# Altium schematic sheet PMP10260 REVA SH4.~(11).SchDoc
size 431 x 279 mm; Date: Not shown in title block; ApprovedBy: Not shown in title block; CheckedBy: Not shown in title block; Author: Not shown in title block; CompanyName: Not shown in title block; Engineer: Not shown in title block; Organization: Not shown in title block; Address1: Not shown in title block; Address2: Not shown in title block; Address3: Not shown in title block; Address4: Not shown in title block; DocumentNumber: 4; Revision: Use project parameter SCH_Rev; SheetNumber: 4; SheetTotal: 4; PageSetup: Record=PageOptions|CenterHorizontal=True|CenterVertical=True|PrintScale=1.00|XCorrection=1.00|YCorrection=1.00|PrintKind=0|BorderSize=5000000|LeftOffset=0|BottomOffset=0|Orientation=2|PaperLength=1000|PaperWidth=1000|Scale=100|PaperSource=15|PrintQuality=600|MediaType=1|DitherType=10|PaperKind=Letter|PrintScaleMode=1
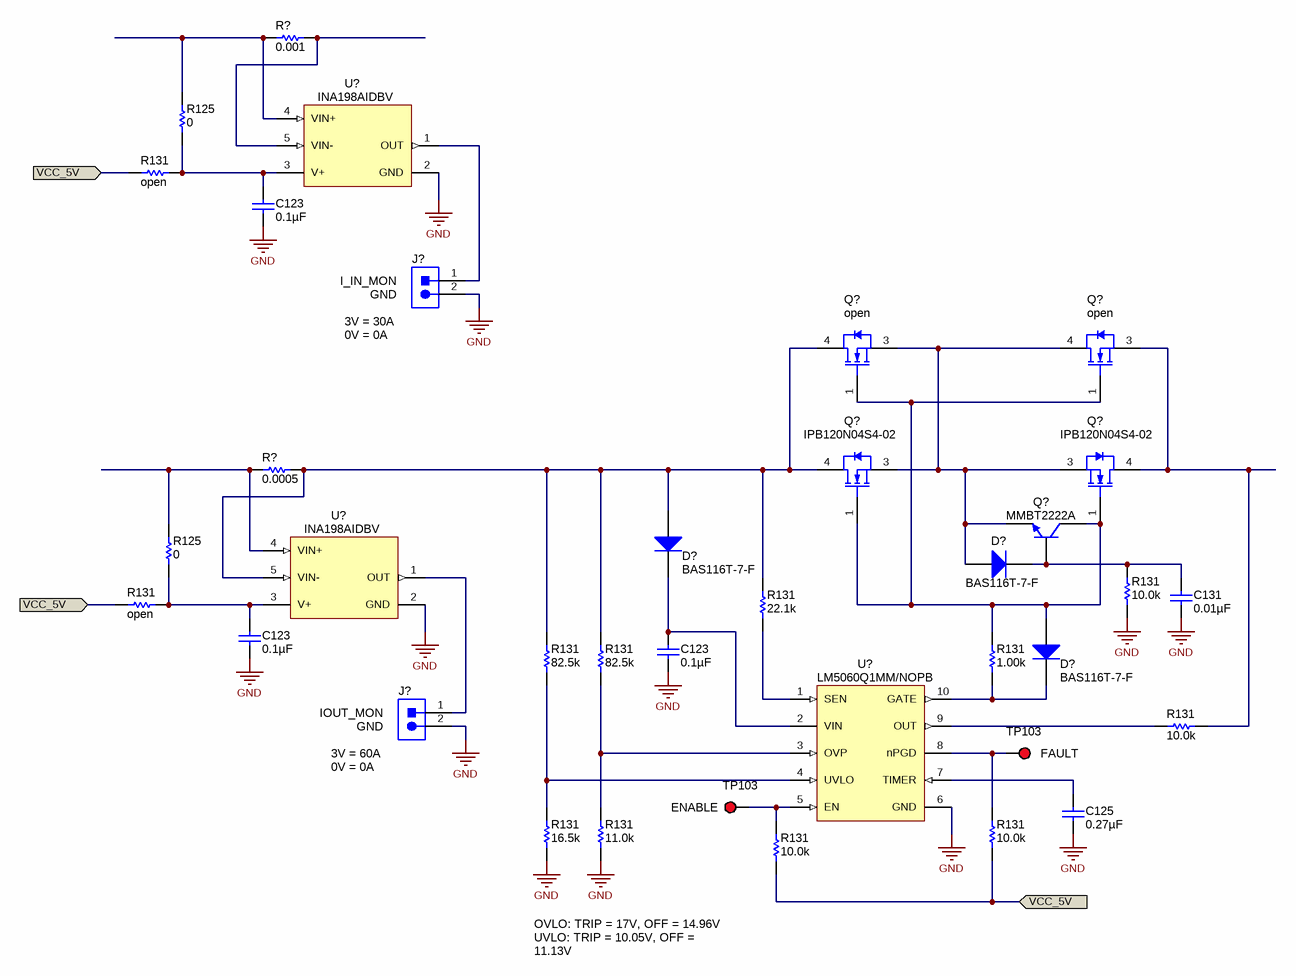
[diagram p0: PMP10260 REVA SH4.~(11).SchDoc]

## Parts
(Parts that share a designator on the sheet are numbered #1, #2 ... from top to bottom, then left to right.)
C123#1  ValueDisplayed: 0.1µF  [0603L]  (hidden comment: C1608X7R1H104K)
C123#2  ValueDisplayed: 0.1µF  [0603L]  (hidden comment: C1608X7R1H104K)
C123#3  ValueDisplayed: 0.1µF  [0603L]  (hidden comment: C1608X7R1H104K)
C125  ValueDisplayed: 0.27µF  [0805_HV]  (hidden comment: 0805YC274KAT2A)
C131  ValueDisplayed: 0.01µF  [0603]  (hidden comment: C1608X7R1H103K)
D?#1  BAS116T-7-F  [SOT-523]
D?#2  BAS116T-7-F  [SOT-523]
D?#3  BAS116T-7-F  [SOT-523]
J?#1  PEC02SAAN  [CONN_PEC02SAAN]  (value not drawn)
J?#2  PEC02SAAN  [CONN_PEC02SAAN]  (value not drawn)
Q?#1  open  [DDPAK]
Q?#2  open  [DDPAK]
Q?#3  IPB120N04S4-02  [DDPAK]
Q?#4  IPB120N04S4-02  [DDPAK]
Q?#5  MMBT2222A  [SOT-23]
R125#1  value 0  [0603L]  (hidden comment: CRCW06030000Z0EA)
R125#2  value 0  [0603L]  (hidden comment: CRCW06030000Z0EA)
R131#1  value open  [0603]
R131#2  value 10.0k  [0603]  (hidden comment: CRCW060310K0FKEA)
R131#3  value open  [0603]
R131#4  value 22.1k  [0603]  (hidden comment: CRCW060322K1FKEA)
R131#5  value 82.5k  [0603]  (hidden comment: CRCW060382K5FKEA)
R131#6  value 82.5k  [0603]  (hidden comment: CRCW060382K5FKEA)
R131#7  value 1.00k  [0603]  (hidden comment: CRCW06031K00FKEA)
R131#8  value 10.0k  [0603]  (hidden comment: CRCW060310K0FKEA)
R131#9  value 16.5k  [0603]  (hidden comment: CRCW060316K5FKEA)
R131#10  value 11.0k  [0603]  (hidden comment: CRCW060311K0FKEA)
R131#11  value 10.0k  [0603]  (hidden comment: CRCW060310K0FKEA)
R131#12  value 10.0k  [0603]  (hidden comment: CRCW060310K0FKEA)
R?#1  value 0.001  [CSS2725_0005]  (hidden comment: CSS2725FT1L00)
R?#2  value 0.0005  [CSS2725_0005]  (hidden comment: CSS2725FTL500)
TP103#1  5010  [Keystone5010]  (value not drawn)
TP103#2  5010  [Keystone5010]  (value not drawn)
U?#1  INA198AIDBV  [DBV0005A_N]
U?#2  INA198AIDBV  [DBV0005A_N]
U?#3  LM5060Q1MM/NOPB  [MUB10A_N]

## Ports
VCC_5V

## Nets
GND: C123#1.2 C123#2.2 C123#3.2 C125.2 C131.2 J?#1.2 J?#2.2 R131#2.1 R131#9.1 R131#10.1 U?#1.2(GND) U?#2.2(GND) U?#3.6(GND)
VCC_5V: R131#1.2 R131#3.2 R131#11.1 R131#12.1 ; port VCC_5V
NetC123#1_1: C123#1.1 R125#1.1 R131#1.1 U?#1.3(V+)
NetC123#2_1: C123#2.1 R125#2.1 R131#3.1 U?#2.3(V+)
NetC123#3_1: C123#3.1 D?#1.3(K) U?#3.2(VIN)
NetC125_1: C125.1 U?#3.7(TIMER)
NetC131_1: C131.1 D?#2.3(K) Q?#5.1(B) R131#2.2
NetD?#1_1: D?#1.1(A) Q?#1.4(D) Q?#3.4(D) R131#4.2 R131#5.2 R131#6.2 R?#2.2 U?#2.5(VIN-)
NetD?#2_1: D?#2.1(A) Q?#1.3(S) Q?#2.4(D) Q?#3.3(S) Q?#4.3(S) Q?#5.2(E)
NetD?#3_1: D?#3.1(A) Q?#1.1(G) Q?#2.1(G) Q?#3.1(G) Q?#4.1(G) Q?#5.3(C) R131#7.1
NetD?#3_3: D?#3.3(K) R131#7.2 U?#3.10(GATE)
NetJ?#1_1: J?#1.1 U?#1.1(OUT)
NetJ?#2_1: J?#2.1 U?#2.1(OUT)
NetQ?#2_3: Q?#2.3(S) Q?#4.4(D) R131#8.1
NetR125#1_2: R125#1.2 R?#1.1 U?#1.4(VIN+)
NetR125#2_2: R125#2.2 R?#2.1 U?#2.4(VIN+)
NetR131#4_1: R131#4.1 U?#3.1(SEN)
NetR131#5_1: R131#5.1 R131#9.2 U?#3.4(UVLO)
NetR131#6_1: R131#6.1 R131#10.2 U?#3.3(OVP)
NetR131#8_2: R131#8.2 U?#3.9(OUT)
NetR131#11_2: R131#11.2 TP103#1.1 U?#3.8(nPGD)
NetR131#12_2: R131#12.2 TP103#2.1 U?#3.5(EN)
NetR?#1_2: R?#1.2 U?#1.5(VIN-)

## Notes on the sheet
- (near J?#1) I_IN_MON
- (near J?#1) GND
- (near J?#1) 3V = 30A
- 0V = 0A
- (near J?#2) 3V = 60A
- (near J?#2) IOUT_MON
- (near J?#2) GND
- (near TP103#1) FAULT
- (near TP103#2) ENABLE
- OVLO: TRIP = 17V, OFF = 14.96V
  UVLO: TRIP = 10.05V, OFF = 11.13V
  OC = 65A/Hot

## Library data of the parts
C123#1-C123#3 = C1608X7R1H104K: CAP, CERM, 0.1uF, 50V, +/-10%, X7R, 0603; Manufacturer: TDK; Polarized: N; CompType: Capacitor; U/M: EA; Cap_F: 0.0000001; Tolerance_%: 10; ESR_Ohm: 0.017; Value1: 0.017 ohm; VDC_V: 50; TaMin_C: -55; TaMax_C: 125; Cap_Case: 0603
C125 = 0805YC274KAT2A: CAP, CERM, 0.27uF, 16V, +/-10%, X7R, 0805; Manufacturer: AVX; Polarized: N; CompType: Capacitor; U/M: EA; Cap_F: 0.00000027; Tolerance_%: 10; ESR_Ohm: 0.015; Value1: 0.015 ohm; VDC_V: 16; TaMin_C: -55; TaMax_C: 125; Cap_Case: 0805
C131 = C1608X7R1H103K: CAP, CERM, 0.01uF, 50V, +/-10%, X7R, 0603; Manufacturer: TDK; Polarized: N; CompType: Capacitor; U/M: EA; Cap_F: 0.00000001; Tolerance_%: 10; ESR_Ohm: 0.0539; Value1: 0.0539 ohm; VDC_V: 50; TaMin_C: -55; TaMax_C: 125
D?#1-D?#3 = BAS116T-7-F: Diode, Switching, 85V, 0.215A, SOT-523; Manufacturer: Diodes Inc.; U/M: EA; Vf_V: 1.25; Value2: 1.25V; Io_A: 0.215; Vr_V: 85; TJmax_C: 150
J?#1 J?#2 = PEC02SAAN: Header, 100mil, 2x1, Tin, TH; Manufacturer: Sullins Connector Solutions; SymbolCreator: a0412235; U/M: EA
Q?#1 Q?#2 = IPB100N10S3-05: MOSFET, open, DDPAK; Alternate Manufacturer: None; U/M: EA; ChType: N; Value1: ? ohm; IdsMax_A: 100
Q?#3 Q?#4 = IPB100N10S3-05: MOSFET, N-CH, 40V, 120A, DDPAK; Manufacturer: Infineon Technologies; Alternate Manufacturer: None; U/M: EA; ChType: N; VdsMax_V: 40; Value1: ? ohm; Vgs_V: 20; IdsMax_A: 100
Q?#5 = MMBT2222A, Fairchild Semiconductor: Transistor, NPN, 40V, 0.15A, SOT-23; CompType: BJT; PNP: 0; NPN: 1; Vceo_V: 40; Vcesat1_V: 0.3; Value: 0.3V; IcRated_A: 0.15; HfeMax: 300; TaMin_C: -55; TaMax_C: 150; U/M: EA
R125#1 R125#2 = CRCW06030000Z0EA: RES, 0 ohm, 5%, 0.1W, 0603; Manufacturer: Vishay-Dale; CompType: Resistor; Value_Code: 0000; Tolerance_%: 5; Power_W: 0.1; VDC_V: 75; TempCo: 200 ppm/C; EIA_Code: E24; U/M: EA
R131#1 R131#3 = CRCW060382K5FKEA: RES, open, 0603; CompType: Resistor; Res_ohm: 82500; Tolerance_%: 1; Value1: 1%; Power_W: 0.1; Value2: 0.1W; TempCo: 100 ppm/C; EIA_Code: E96; U/M: EA
R131#2 R131#8 R131#11 R131#12 = CRCW060310K0FKEA: RES, 10.0k ohm, 1%, 0.1W, 0603; Manufacturer: Vishay-Dale; CompType: Resistor; Res_ohm: 10000; Value_Code: 10k0; Tolerance_%: 1; Power_W: 0.1; VDC_V: 75; TempCo: 100 ppm/C; EIA_Code: E96; U/M: EA
R131#4 = CRCW060322K1FKEA: RES, 22.1k ohm, 1%, 0.1W, 0603; Manufacturer: Vishay-Dale; CompType: Resistor; Res_ohm: 22100; Value_Code: 22k1; Tolerance_%: 1; Power_W: 0.1; VDC_V: 75; TempCo: 100 ppm/C; EIA_Code: E96; U/M: EA
R131#5 R131#6 = CRCW060382K5FKEA: RES, 82.5k ohm, 1%, 0.1W, 0603; Manufacturer: Vishay-Dale; CompType: Resistor; Res_ohm: 82500; Value_Code: 82k5; Tolerance_%: 1; Power_W: 0.1; VDC_V: 75; TempCo: 100 ppm/C; EIA_Code: E96; U/M: EA
R131#7 = CRCW06031K00FKEA: RES, 1.00k ohm, 1%, 0.1W, 0603; Manufacturer: Vishay-Dale; CompType: Resistor; Res_ohm: 1000; Value_Code: 1k00; Tolerance_%: 1; Power_W: 0.1; VDC_V: 75; TempCo: 100 ppm/C; EIA_Code: E96; U/M: EA
R131#9 = CRCW060316K5FKEA: RES, 16.5k ohm, 1%, 0.1W, 0603; Manufacturer: Vishay-Dale; CompType: Resistor; Res_ohm: 16500; Value_Code: 16k5; Tolerance_%: 1; Power_W: 0.1; VDC_V: 75; TempCo: 100 ppm/C; EIA_Code: E96; U/M: EA
R131#10 = CRCW060311K0FKEA: RES, 11.0k ohm, 1%, 0.1W, 0603; Manufacturer: Vishay-Dale; CompType: Resistor; Res_ohm: 11000; Value_Code: 11k0; Tolerance_%: 1; Power_W: 0.1; VDC_V: 75; TempCo: 100 ppm/C; EIA_Code: E96; U/M: EA
R?#1 = CSS2725FTL500: RES, 0.001 ohm, 1%, 4W, RES_2725; Manufacturer: Stackpole Electronics Inc; CompType: Resistor; Res_ohm: 0.0005; Value_Code: R001; Tolerance_%: 1; Power_W: 4; TempCo: 50 ppm/C; U/M: EA
R?#2 = CSS2725FTL500: RES, 0.0005 ohm, 1%, 4W, RES_2725; Manufacturer: Stackpole Electronics Inc; CompType: Resistor; Value_Code: R0005; Tolerance_%: 1; Power_W: 4; TempCo: 50 ppm/C; U/M: EA
TP103#1 TP103#2 = 5010: Test Point, Multipurpose, Red, TH; Manufacturer: Keystone; CompType: Test Point Loop; U/M: EA
U?#1 U?#2 = INA198AIDBV: CURRENT SHUNT MONITOR -16V to +80V Common-Mode Range, DBV0005A; Alternate Manufacturer: None; Manufacturer: Texas Instruments; SymbolCreator: a0411947; CompType: IC; U/M: EA
U?#3 = LM5060Q1MM/NOPB: High-Side Protection Controller with Low Quiescent Current, 10-pin MSOP, Pb-Free; Manufacturer: National Semiconductor; PackageTopMarking: ZXTT*SZAB; PowerWise: N; CompType: Switcher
